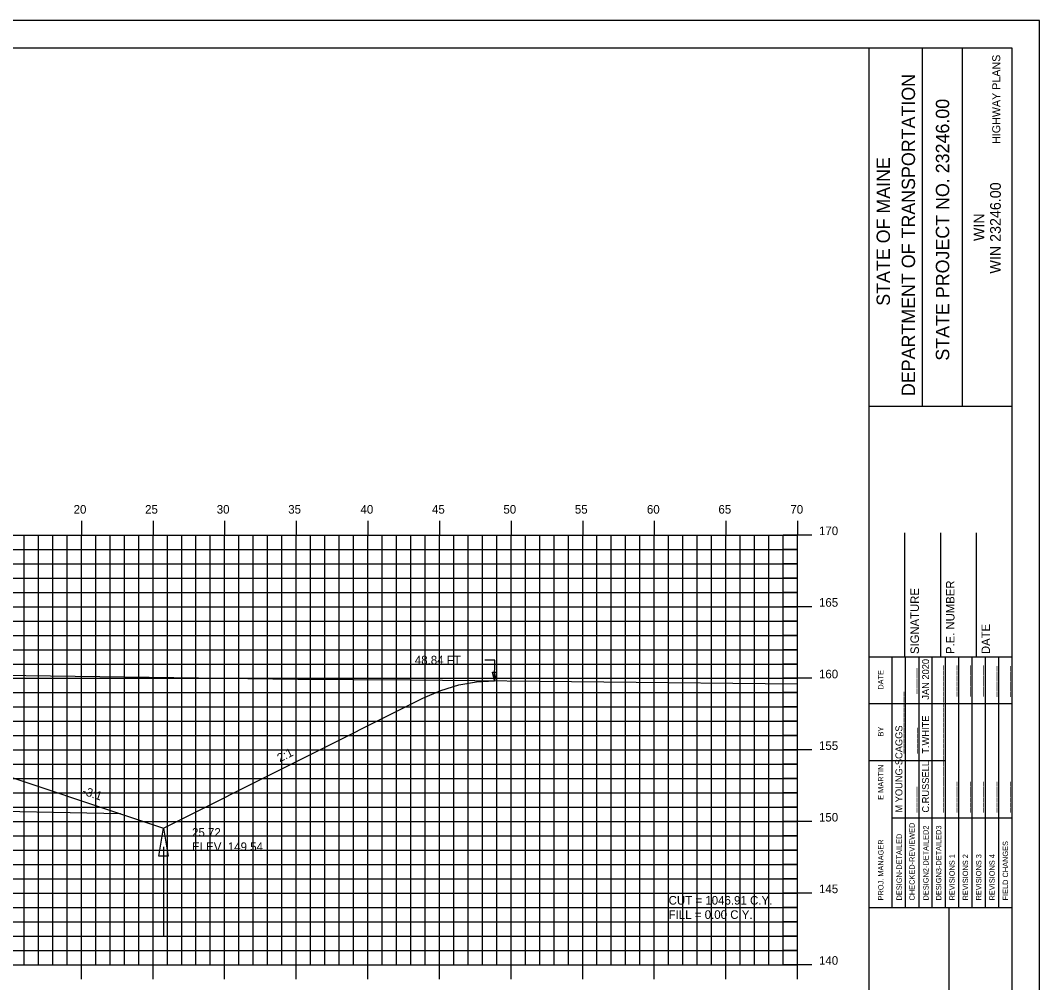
# Model space of a CAD drawing. Extents: x 1143420 to 1143590, y 608981 to 609091.
# Drawn here: x 1143518.8 to 1143590, y 609024.1 to 609091.3 of the extents above; entities that cross this region are included whole.
import ezdxf

# ---------------------------------------------------------------- set-up
doc = ezdxf.new("R2010")
doc.units = 0
for name, color, linetype in [('ANNOTATION', 7, 'Continuous'), ('BORDER', 7, 'Continuous'), ('D_Drainage_Ditch_Line', 7, 'Continuous'), ('D_Roadway_SlopeLines', 7, 'Continuous'), ('D_Roadway_SubGrade', 7, 'Continuous'), ('D_Text_Standard', 7, 'Continuous'), ('H_V ANNOTATION', 7, 'Continuous'), ('HIGHWAY_TITLE', 7, 'Continuous'), ('MAJOR', 7, 'Continuous'), ('MINOR', 7, 'Continuous'), ('PLOT BOUNDARY', 7, 'Continuous'), ('S_Roadway_Centerline', 7, 'Continuous')]:
    doc.layers.add(name, color=color, linetype=linetype)

msp = doc.modelspace()

# ---------------------------------------------------------------- linework, layer by layer
msp.add_lwpolyline([(1143454.133, 609045.188), (1143455.383, 609045.133), (1143456.633, 609044.915), (1143457.883, 609044.534), (1143459.133, 609043.99), (1143477.355, 609034.879), (1143480.355, 609035.879), (1143488.079, 609038.454), (1143488.08, 609038.454), (1143492.08, 609038.614), (1143503.08, 609038.834), (1143514.08, 609038.614), (1143518.08, 609038.454), (1143525.803, 609035.879), (1143528.803, 609034.879), (1143546.922, 609043.939), (1143548.172, 609044.484), (1143549.422, 609044.87), (1143550.672, 609045.096), (1143551.922, 609045.163)])
at = {"layer": 'BORDER'}
for p, q in [((1143578.08, 608984.335), (1143578.08, 609089.335)), ((1143581.808, 609064.332), (1143581.808, 609089.332)), ((1143584.603, 609064.332), (1143584.603, 609089.332)), ((1143578.081, 609064.329), (1143588.08, 609064.329)), ((1143580.58, 609046.838), (1143580.58, 609055.485)), ((1143583.08, 609046.838), (1143583.08, 609055.485)), ((1143585.58, 609046.838), (1143585.58, 609055.485)), ((1143578.08, 609046.838), (1143588.08, 609046.838)), ((1143578.08, 609029.338), (1143588.08, 609029.338)), ((1143583.671, 608994.338), (1143583.671, 609029.338))]:
    msp.add_line(p, q, dxfattribs=at)
msp.add_lwpolyline([(1143428.08, 608984.335), (1143588.08, 608984.335), (1143588.08, 609089.335), (1143428.08, 609089.335)], close=True, dxfattribs=at)
for points in [[(1143579.695, 609043.588), (1143579.695, 609046.838)], [(1143580.627, 609029.341), (1143580.627, 609046.838)], [(1143581.559, 609046.838), (1143581.559, 609029.341)], [(1143582.491, 609029.341), (1143582.491, 609046.838)], [(1143583.422, 609029.341), (1143583.422, 609046.838)], [(1143584.354, 609029.341), (1143584.354, 609046.838)], [(1143585.286, 609029.341), (1143585.286, 609046.838)], [(1143586.217, 609029.341), (1143586.217, 609046.838)], [(1143587.149, 609029.341), (1143587.149, 609046.838)], [(1143579.696, 609029.341), (1143579.696, 609046.132)], [(1143578.08, 609043.588), (1143588.08, 609043.588)], [(1143578.08, 609039.588), (1143579.696, 609039.588)], [(1143579.695, 609039.588), (1143583.421, 609039.588)], [(1143579.695, 609035.588), (1143588.08, 609035.588)]]:
    msp.add_lwpolyline(points, dxfattribs=at)
at = {"layer": 'D_Drainage_Ditch_Line'}
msp.add_line((1143528.803, 609033.567), (1143528.803, 609027.323), dxfattribs=at)
msp.add_lwpolyline([(1143529.131, 609032.911), (1143528.475, 609032.911), (1143528.803, 609034.879)], close=True, dxfattribs=at)
at = {"layer": 'D_Roadway_SlopeLines'}
for points in [[(1143528.803, 609034.879), (1143546.922, 609043.939), (1143548.172, 609044.484), (1143549.422, 609044.87), (1143550.672, 609045.096), (1143551.922, 609045.163)], [(1143525.803, 609035.879), (1143528.803, 609034.879)]]:
    msp.add_lwpolyline(points, dxfattribs=at)
at = {"layer": 'D_Roadway_SubGrade'}
msp.add_lwpolyline([(1143514.08, 609038.197), (1143514.08, 609038.364), (1143518.08, 609038.204), (1143518.08, 609038.454), (1143518.08, 609038.454), (1143525.803, 609035.879), (1143514.08, 609036.114)], close=True, dxfattribs=at)
at = {"layer": 'D_Text_Standard'}
msp.add_lwpolyline([(1143551.922, 609045.189), (1143551.938, 609046.611), (1143551.258, 609046.611)], dxfattribs=at)
msp.add_lwpolyline([(1143551.922, 609045.189), (1143551.783, 609045.772), (1143552.074, 609045.769)], close=True, dxfattribs=at)
at = {"layer": 'MAJOR'}
for p, q in [((1143523.08, 609056.337), (1143523.08, 609055.335)), ((1143528.08, 609056.337), (1143528.08, 609055.335)), ((1143533.08, 609056.337), (1143533.08, 609055.335)), ((1143538.08, 609056.337), (1143538.08, 609055.335)), ((1143543.08, 609056.337), (1143543.08, 609055.335)), ((1143548.08, 609056.337), (1143548.08, 609055.335)), ((1143553.08, 609056.337), (1143553.08, 609055.335)), ((1143558.08, 609056.337), (1143558.08, 609055.335)), ((1143563.08, 609056.337), (1143563.08, 609055.335)), ((1143568.08, 609056.337), (1143568.08, 609055.335)), ((1143573.08, 609056.337), (1143573.08, 609055.335)), ((1143433.08, 609055.335), (1143573.08, 609055.335)), ((1143433.08, 609055.335), (1143573.08, 609055.335)), ((1143523.08, 609025.335), (1143523.08, 609055.335)), ((1143528.08, 609025.335), (1143528.08, 609055.335)), ((1143533.08, 609025.335), (1143533.08, 609055.335)), ((1143538.08, 609025.335), (1143538.08, 609055.335)), ((1143543.08, 609025.335), (1143543.08, 609055.335)), ((1143548.08, 609025.335), (1143548.08, 609055.335)), ((1143553.08, 609025.335), (1143553.08, 609055.335)), ((1143558.08, 609025.335), (1143558.08, 609055.335)), ((1143563.08, 609025.335), (1143563.08, 609055.335)), ((1143568.08, 609025.335), (1143568.08, 609055.335)), ((1143574.082, 609055.335), (1143572.078, 609055.335)), ((1143573.08, 609025.335), (1143573.08, 609055.335)), ((1143573.08, 609025.335), (1143573.08, 609055.335)), ((1143433.08, 609050.335), (1143573.08, 609050.335)), ((1143574.082, 609050.335), (1143572.078, 609050.335)), ((1143433.08, 609045.335), (1143573.08, 609045.335)), ((1143574.082, 609045.335), (1143572.078, 609045.335)), ((1143433.08, 609040.335), (1143573.08, 609040.335)), ((1143574.082, 609040.335), (1143572.078, 609040.335)), ((1143433.08, 609035.335), (1143573.08, 609035.335)), ((1143574.082, 609035.335), (1143572.078, 609035.335)), ((1143433.08, 609030.335), (1143573.08, 609030.335)), ((1143574.082, 609030.335), (1143572.078, 609030.335)), ((1143433.08, 609025.335), (1143573.08, 609025.335)), ((1143433.08, 609025.335), (1143573.08, 609025.335)), ((1143523.08, 609024.333), (1143523.08, 609025.335)), ((1143528.08, 609024.333), (1143528.08, 609025.335)), ((1143533.08, 609024.333), (1143533.08, 609025.335)), ((1143538.08, 609024.333), (1143538.08, 609025.335)), ((1143543.08, 609024.333), (1143543.08, 609025.335)), ((1143548.08, 609024.333), (1143548.08, 609025.335)), ((1143553.08, 609024.333), (1143553.08, 609025.335)), ((1143558.08, 609024.333), (1143558.08, 609025.335)), ((1143563.08, 609024.333), (1143563.08, 609025.335)), ((1143568.08, 609024.333), (1143568.08, 609025.335)), ((1143574.082, 609025.335), (1143572.078, 609025.335)), ((1143573.08, 609024.333), (1143573.08, 609025.335))]:
    msp.add_line(p, q, dxfattribs=at)
at = {"layer": 'MINOR'}
for p, q in [((1143519.08, 609025.335), (1143519.08, 609055.335)), ((1143520.08, 609025.335), (1143520.08, 609055.335)), ((1143521.08, 609025.335), (1143521.08, 609055.335)), ((1143522.08, 609025.335), (1143522.08, 609055.335)), ((1143524.08, 609025.335), (1143524.08, 609055.335)), ((1143525.08, 609025.335), (1143525.08, 609055.335)), ((1143526.08, 609025.335), (1143526.08, 609055.335)), ((1143527.08, 609025.335), (1143527.08, 609055.335)), ((1143529.08, 609025.335), (1143529.08, 609055.335)), ((1143530.08, 609025.335), (1143530.08, 609055.335)), ((1143531.08, 609025.335), (1143531.08, 609055.335)), ((1143532.08, 609025.335), (1143532.08, 609055.335)), ((1143534.08, 609025.335), (1143534.08, 609055.335)), ((1143535.08, 609025.335), (1143535.08, 609055.335)), ((1143536.08, 609025.335), (1143536.08, 609055.335)), ((1143537.08, 609025.335), (1143537.08, 609055.335)), ((1143539.08, 609025.335), (1143539.08, 609055.335)), ((1143540.08, 609025.335), (1143540.08, 609055.335)), ((1143541.08, 609025.335), (1143541.08, 609055.335)), ((1143542.08, 609025.335), (1143542.08, 609055.335)), ((1143544.08, 609025.335), (1143544.08, 609055.335)), ((1143545.08, 609025.335), (1143545.08, 609055.335)), ((1143546.08, 609025.335), (1143546.08, 609055.335)), ((1143547.08, 609025.335), (1143547.08, 609055.335)), ((1143549.08, 609025.335), (1143549.08, 609055.335)), ((1143550.08, 609025.335), (1143550.08, 609055.335)), ((1143551.08, 609025.335), (1143551.08, 609055.335)), ((1143552.08, 609025.335), (1143552.08, 609055.335)), ((1143554.08, 609025.335), (1143554.08, 609055.335)), ((1143555.08, 609025.335), (1143555.08, 609055.335)), ((1143556.08, 609025.335), (1143556.08, 609055.335)), ((1143557.08, 609025.335), (1143557.08, 609055.335)), ((1143559.08, 609025.335), (1143559.08, 609055.335)), ((1143560.08, 609025.335), (1143560.08, 609055.335)), ((1143561.08, 609025.335), (1143561.08, 609055.335)), ((1143562.08, 609025.335), (1143562.08, 609055.335)), ((1143564.08, 609025.335), (1143564.08, 609055.335)), ((1143565.08, 609025.335), (1143565.08, 609055.335)), ((1143566.08, 609025.335), (1143566.08, 609055.335)), ((1143567.08, 609025.335), (1143567.08, 609055.335)), ((1143569.08, 609025.335), (1143569.08, 609055.335)), ((1143570.08, 609025.335), (1143570.08, 609055.335)), ((1143571.08, 609025.335), (1143571.08, 609055.335)), ((1143572.08, 609025.335), (1143572.08, 609055.335)), ((1143433.08, 609054.335), (1143573.08, 609054.335)), ((1143573.08, 609054.335), (1143572.078, 609054.335)), ((1143433.08, 609053.335), (1143573.08, 609053.335)), ((1143573.08, 609053.335), (1143572.078, 609053.335)), ((1143433.08, 609052.335), (1143573.08, 609052.335)), ((1143573.08, 609052.335), (1143572.078, 609052.335)), ((1143433.08, 609051.335), (1143573.08, 609051.335)), ((1143573.08, 609051.335), (1143572.078, 609051.335)), ((1143433.08, 609049.335), (1143573.08, 609049.335)), ((1143573.08, 609049.335), (1143572.078, 609049.335)), ((1143433.08, 609048.335), (1143573.08, 609048.335)), ((1143573.08, 609048.335), (1143572.078, 609048.335)), ((1143433.08, 609047.335), (1143573.08, 609047.335)), ((1143573.08, 609047.335), (1143572.078, 609047.335)), ((1143433.08, 609046.335), (1143573.08, 609046.335)), ((1143573.08, 609046.335), (1143572.078, 609046.335)), ((1143433.08, 609044.335), (1143573.08, 609044.335)), ((1143573.08, 609044.335), (1143572.078, 609044.335)), ((1143433.08, 609043.335), (1143573.08, 609043.335)), ((1143573.08, 609043.335), (1143572.078, 609043.335)), ((1143433.08, 609042.335), (1143573.08, 609042.335)), ((1143573.08, 609042.335), (1143572.078, 609042.335)), ((1143433.08, 609041.335), (1143573.08, 609041.335)), ((1143573.08, 609041.335), (1143572.078, 609041.335)), ((1143433.08, 609039.335), (1143573.08, 609039.335)), ((1143573.08, 609039.335), (1143572.078, 609039.335)), ((1143433.08, 609038.335), (1143573.08, 609038.335)), ((1143573.08, 609038.335), (1143572.078, 609038.335)), ((1143433.08, 609037.335), (1143573.08, 609037.335)), ((1143573.08, 609037.335), (1143572.078, 609037.335)), ((1143433.08, 609036.335), (1143573.08, 609036.335)), ((1143573.08, 609036.335), (1143572.078, 609036.335)), ((1143433.08, 609034.335), (1143573.08, 609034.335)), ((1143573.08, 609034.335), (1143572.078, 609034.335)), ((1143433.08, 609033.335), (1143573.08, 609033.335)), ((1143573.08, 609033.335), (1143572.078, 609033.335)), ((1143433.08, 609032.335), (1143573.08, 609032.335)), ((1143573.08, 609032.335), (1143572.078, 609032.335)), ((1143433.08, 609031.335), (1143573.08, 609031.335)), ((1143573.08, 609031.335), (1143572.078, 609031.335)), ((1143433.08, 609029.335), (1143573.08, 609029.335)), ((1143573.08, 609029.335), (1143572.078, 609029.335)), ((1143433.08, 609028.335), (1143573.08, 609028.335)), ((1143573.08, 609028.335), (1143572.078, 609028.335)), ((1143433.08, 609027.335), (1143573.08, 609027.335)), ((1143573.08, 609027.335), (1143572.078, 609027.335)), ((1143433.08, 609026.335), (1143573.08, 609026.335)), ((1143573.08, 609026.335), (1143572.078, 609026.335))]:
    msp.add_line(p, q, dxfattribs=at)
at = {"layer": 'PLOT BOUNDARY'}
msp.add_lwpolyline([(1143419.986, 608981.276), (1143589.986, 608981.276), (1143589.986, 609091.276), (1143419.986, 609091.276)], close=True, dxfattribs=at)
at = {"layer": 'S_Roadway_Centerline'}
msp.add_lwpolyline([(1143433.08, 609044.546), (1143436.28, 609044.822), (1143439.921, 609044.888), (1143456.939, 609045.247), (1143459.16, 609044.533), (1143466.012, 609041.915), (1143468.915, 609042.679), (1143469.816, 609042.947), (1143471.462, 609043.097), (1143472.407, 609043.168), (1143482.258, 609043.346), (1143483.051, 609043.354), (1143493.938, 609043.106), (1143494.247, 609043.095), (1143497.626, 609043.011), (1143497.719, 609043.007), (1143500.594, 609042.08), (1143500.644, 609042.068), (1143501.744, 609042.494), (1143510.556, 609045.639), (1143534.693, 609045.32), (1143538.189, 609045.275), (1143546.024, 609045.224), (1143573.08, 609044.943)], dxfattribs=at)

# ---------------------------------------------------------------- texts
at = {"layer": 'ANNOTATION'}
for s, rotation, p in [('2:1', 26.56505, (1143536.935, 609039.463)), ('-3:1', 341.56521, (1143523.091, 609037.237))]:
    msp.add_text(s, height=0.6, rotation=rotation, dxfattribs=at).set_placement(p)
at = {"layer": 'BORDER'}
for s, height, p in [('DEPARTMENT OF TRANSPORTATION', 0.93176, (1143581.287, 609065.041)), ('STATE PROJECT NO. 23246.00', 0.93176, (1143583.672, 609067.517)), ('STATE OF MAINE', 0.93176, (1143579.535, 609071.347)), ('WIN 23246.00', 0.74527, (1143587.275, 609073.596)), ('WIN', 0.7453, (1143586.117, 609075.865)), ('P.E. NUMBER', 0.59055, (1143584.041, 609047.03)), ('SIGNATURE', 0.5906, (1143581.56, 609047.03)), ('DATE', 0.5906, (1143586.521, 609047.03)), ('JAN 2020', 0.4845, (1143582.266, 609043.843)), ('DATE', 0.3714, (1143579.084, 609044.544)), ('_____', 0.4845, (1143581.297, 609044.243)), ('______', 0.4845, (1143583.161, 609044.063)), ('______', 0.4845, (1143584.092, 609044.065)), ('______', 0.4845, (1143585.024, 609044.067)), ('______', 0.4845, (1143585.956, 609044.067)), ('______', 0.4845, (1143586.887, 609044.036)), ('______', 0.4845, (1143587.819, 609044.036)), ('____________', 0.48455, (1143580.403, 609040.073)), ('____________', 0.48455, (1143583.161, 609040.073)), ('T.WHITE', 0.4845, (1143582.266, 609040.073)), ('M YOUNG-SCAGGS', 0.48455, (1143580.403, 609035.961)), ('BY', 0.3714, (1143579.084, 609041.273)), ('_____', 0.4845, (1143581.334, 609040.073)), ('____________', 0.48455, (1143583.161, 609035.961)), ('E MARTIN', 0.3727, (1143579.084, 609036.855)), ('C.RUSSELL', 0.4845, (1143582.266, 609035.961)), ('_____', 0.4845, (1143581.297, 609035.961)), ('______', 0.4845, (1143584.092, 609035.961)), ('______', 0.4845, (1143585.024, 609035.961)), ('______', 0.4845, (1143585.956, 609035.961)), ('______', 0.4845, (1143586.887, 609035.961)), ('______', 0.4845, (1143587.819, 609035.961)), ('CHECKED-REVIEWED', 0.37275, (1143581.261, 609029.826)), ('DESIGN3-DETAILED3', 0.37275, (1143583.124, 609029.826)), ('DESIGN-DETAILED', 0.37275, (1143580.366, 609029.826)), ('DESIGN2-DETAILED2', 0.37275, (1143582.23, 609029.826)), ('PROJ. MANAGER', 0.37275, (1143579.084, 609029.826)), ('FIELD CHANGES', 0.37275, (1143587.783, 609029.826)), ('REVISIONS 1', 0.37275, (1143584.056, 609029.826)), ('REVISIONS 2', 0.37275, (1143584.988, 609029.826)), ('REVISIONS 3', 0.37275, (1143585.919, 609029.826)), ('REVISIONS 4', 0.37275, (1143586.851, 609029.826))]:
    msp.add_text(s, height=height, rotation=90, dxfattribs=at).set_placement(p)
at = {"layer": 'D_Text_Standard'}
for s, p in [('48.84 FT', (1143546.36, 609046.311)), ('25.72', (1143530.803, 609034.279)), ('ELEV. 149.54', (1143530.803, 609033.277)), ('CUT = 1046.91 C.Y.', (1143564.08, 609029.535)), ('FILL = 0.00 C.Y.', (1143564.08, 609028.539))]:
    msp.add_text(s, height=0.6, dxfattribs=at).set_placement(p)
at = {"layer": 'H_V ANNOTATION'}
for s, p in [('20', (1143522.534, 609056.835)), ('25', (1143527.526, 609056.835)), ('30', (1143532.528, 609056.835)), ('35', (1143537.52, 609056.835)), ('40', (1143542.566, 609056.835)), ('45', (1143547.558, 609056.835)), ('50', (1143552.544, 609056.835)), ('55', (1143557.536, 609056.835)), ('60', (1143562.566, 609056.835)), ('65', (1143567.558, 609056.835)), ('70', (1143572.582, 609056.835)), ('170', (1143574.58, 609055.335)), ('165', (1143574.58, 609050.335)), ('160', (1143574.58, 609045.335)), ('155', (1143574.58, 609040.335)), ('150', (1143574.58, 609035.335)), ('145', (1143574.58, 609030.335)), ('140', (1143574.58, 609025.335))]:
    msp.add_text(s, height=0.6, dxfattribs=at).set_placement(p)
at = {"layer": 'HIGHWAY_TITLE'}
msp.add_text('HIGHWAY PLANS', height=0.55901, rotation=90, dxfattribs=at).set_placement((1143587.238, 609082.65))

doc.saveas('drawing.dxf')
